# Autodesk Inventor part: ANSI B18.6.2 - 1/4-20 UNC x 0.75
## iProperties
Comments: To add or edit properties for Autodesk Inventor files, use iProperties.
Created: 2005-06
Part Number: ANSI B18.6.2 - 1/4-20 UNC x 0.75
Vendor: Autodesk Inc.
Document SubType Name: Modeling
Designer: John Blackburn
Material: Default
Description: Slotted Flat Countersunk Head Cap Screw
Standard: ANSI B18.6.2
Size Designation: 1/4-20 UNC x 0.75
Alert: To add or edit properties for Autodesk Inventor files, use iProperties.
Control State: 0
Master: False
Checked Out: False
Shininess: 64.0
Length Units: 11272
Angle Units: 11279
Time Units: 11290
Mass Units: 11286
Length Display Precision: 3
Angle Display Precision: 2
Compacted: True
EGR: 3
Classification: un/spsc 31161513
Density: 0.0
Volumn: 0.0
Area: 0.0
PropertySet Name: Model Information
Author: John Blackburn
Revision Number: 8
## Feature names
1. Body [Revolution]
2. Slot [Extrusion]
3. Chamfer1
